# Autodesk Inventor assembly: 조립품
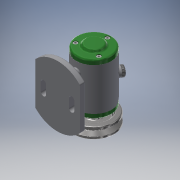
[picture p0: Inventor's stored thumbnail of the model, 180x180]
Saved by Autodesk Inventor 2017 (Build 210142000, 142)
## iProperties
Part Number: 조립품
Material: 일반
Document SubType Name: Assembly
Designer: 601-19
Author: 601-19
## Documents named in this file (14)
- C:\Users\601-19\Desktop\720206V1021\조립품.iam
- C:\Users\601-19\Desktop\720206V1021\V벨트풀리.ipt
- C:\Users\601-19\Desktop\720206V1021\고무 캡.ipt
- C:\Users\601-19\Desktop\720206V1021\너트 M8.ipt
- C:\Users\601-19\Desktop\720206V1021\뒤커버.ipt
- C:\Users\601-19\Desktop\720206V1021\베어링 6002.ipt
- C:\Users\601-19\Desktop\720206V1021\본체.ipt
- C:\Users\601-19\Desktop\720206V1021\볼트 M4 x 10.ipt
- C:\Users\601-19\Desktop\720206V1021\스프링와셔 8.ipt
- C:\Users\601-19\Desktop\720206V1021\앞커버.ipt
- C:\Users\601-19\Desktop\720206V1021\오일 실 15 x 25 x 7.ipt
- C:\Users\601-19\Desktop\720206V1021\축.ipt
- C:\Users\601-19\Desktop\720206V1021\키 3 x 3 x 12.ipt
- C:\Users\601-19\Desktop\720206V1021\평와셔 8 x 17.ipt
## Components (2 placed, 2 different names)
1. V벨트풀리:1 — 각도:1
2. 고무 캡:1
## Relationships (1: Angle 1)
- 각도:1 [Angle]: V벨트풀리:1
